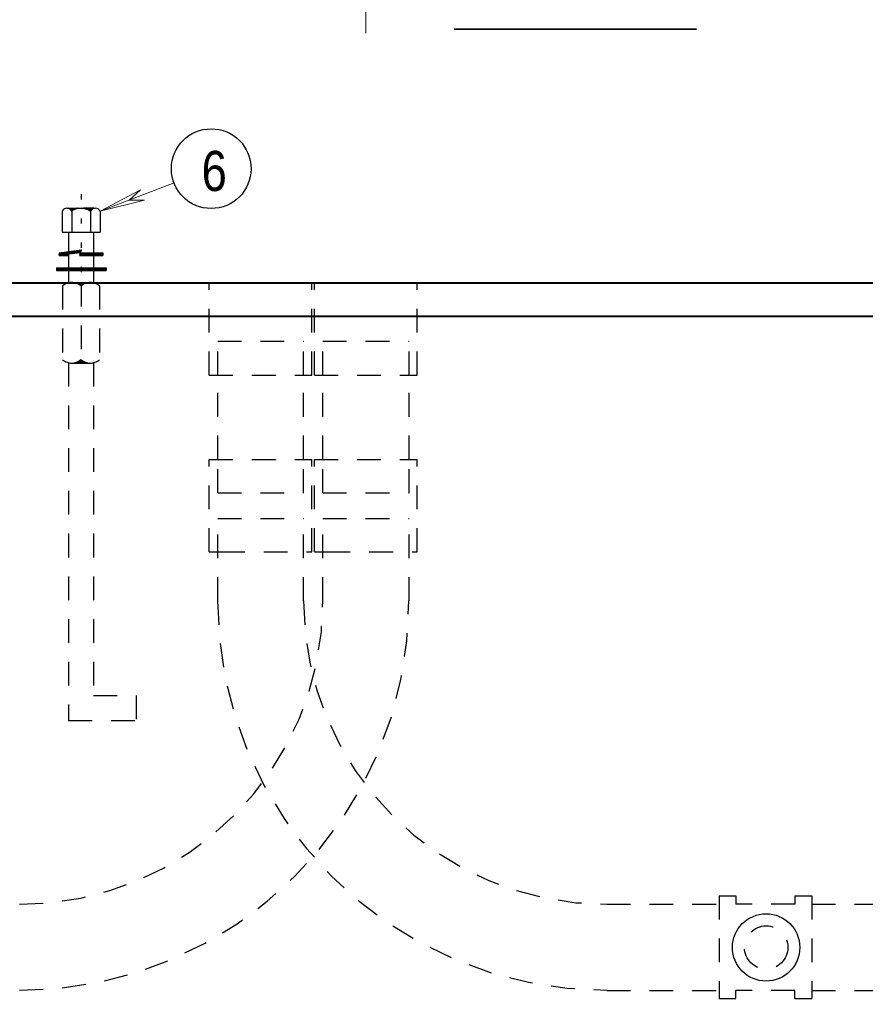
# Model space of a CAD drawing. Extents: x 312583 to 312854, y 144419 to 144597.
# Drawn here: x 312801.16 to 312817.2, y 144530.65 to 144549.21 of the extents above; entities that cross this region are included whole.
import ezdxf

# ---------------------------------------------------------------- set-up
doc = ezdxf.new("R2010")
doc.units = 0
doc.header["$LTSCALE"] = 0.3
doc.linetypes.add('DOTTED', pattern=[1.5, 0.3, -1.2])
doc.linetypes.add('SHORT_DASHED', pattern=[2.7, 1.5, -1.2])
doc.layers.add('1', color=7, linetype='Continuous', lineweight=25)
doc.layers.add('2', color=7, linetype='Continuous', lineweight=13)

msp = doc.modelspace()

# ---------------------------------------------------------------- linework, layer by layer
at = {"layer": '1', "linetype": 'DOTTED'}
msp.add_line((312802.3276, 144545.9033), (312802.3276, 144544.2243), dxfattribs=at)
at = {"layer": '1'}
for p, q in [((312801.9673, 144545.5813), (312801.9673, 144545.1826)), ((312802.0593, 144545.6349), (312802.596, 144545.6349)), ((312802.1513, 144545.5813), (312802.1513, 144545.1826)), ((312802.504, 144545.5813), (312802.504, 144545.1826)), ((312802.688, 144545.5813), (312802.688, 144545.1826)), ((312801.9673, 144545.1826), (312802.688, 144545.1826)), ((312802.09, 144545.1826), (312802.09, 144544.2243)), ((312802.5653, 144545.1826), (312802.5653, 144544.2243)), ((312801.9136, 144544.7916), (312801.9136, 144544.7379)), ((312802.3123, 144544.7916), (312802.7416, 144544.7916)), ((312802.7416, 144544.7916), (312802.7416, 144544.7379)), ((312802.297, 144544.7379), (312802.7416, 144544.7379)), ((312801.86, 144544.5079), (312802.803, 144544.5079)), ((312801.86, 144544.5079), (312801.86, 144544.4543)), ((312801.86, 144544.4926), (312802.803, 144544.4926)), ((312801.86, 144544.4773), (312802.803, 144544.4773)), ((312801.86, 144544.4619), (312802.803, 144544.4619)), ((312801.86, 144544.4543), (312802.803, 144544.4543)), ((312802.803, 144544.5079), (312802.803, 144544.4543)), ((312802.09, 144544.2243), (312802.5653, 144544.2243)), ((312802.1513, 144544.2243), (312802.504, 144544.2243))]:
    msp.add_line(p, q, dxfattribs=at)
at = {"layer": '1', "lineweight": 40}
for p, q in [((312778.6606, 144544.2243), (312839.994, 144544.2243)), ((312794.3773, 144543.5879), (312818.19, 144543.5879))]:
    msp.add_line(p, q, dxfattribs=at)
at = {"layer": '1', "linetype": 'SHORT_DASHED'}
for p, q in [((312801.975, 144544.1629), (312801.975, 144542.7676)), ((312802.3276, 144544.2243), (312802.3276, 144542.6986)), ((312802.6803, 144544.1629), (312802.6803, 144542.7676)), ((312804.758, 144542.4686), (312804.758, 144544.2243)), ((312806.7053, 144542.4686), (312806.7053, 144544.2243)), ((312806.7513, 144542.4686), (312806.7513, 144544.2243)), ((312808.6986, 144542.4686), (312808.6986, 144544.2243)), ((312804.919, 144543.1126), (312806.5443, 144543.1126)), ((312804.919, 144542.4686), (312804.919, 144543.1126)), ((312806.5443, 144542.4686), (312806.5443, 144543.1126)), ((312806.9123, 144543.1126), (312808.5453, 144543.1126)), ((312806.9123, 144542.4686), (312806.9123, 144543.1126)), ((312808.5453, 144542.4686), (312808.5453, 144543.1126)), ((312802.09, 144542.7063), (312802.09, 144535.9213)), ((312802.1513, 144542.6986), (312802.504, 144542.6986)), ((312802.5653, 144542.7063), (312802.5653, 144536.3966)), ((312804.758, 144542.4686), (312806.7053, 144542.4686)), ((312804.919, 144540.8739), (312804.919, 144542.4686)), ((312806.5443, 144540.8739), (312806.5443, 144542.4686)), ((312806.7513, 144542.4686), (312808.6986, 144542.4686)), ((312806.9123, 144540.8739), (312806.9123, 144542.4686)), ((312808.5453, 144540.8739), (312808.5453, 144542.4686)), ((312804.758, 144539.1183), (312804.758, 144540.8739)), ((312804.758, 144540.8739), (312806.7053, 144540.8739)), ((312804.919, 144540.2376), (312804.919, 144540.8739)), ((312806.5443, 144540.2376), (312806.5443, 144540.8739)), ((312806.7513, 144539.1183), (312806.7513, 144540.8739)), ((312806.7513, 144540.8739), (312808.6986, 144540.8739)), ((312806.9123, 144540.2376), (312806.9123, 144540.8739)), ((312808.5453, 144540.2376), (312808.5453, 144540.8739)), ((312804.919, 144540.2376), (312806.5443, 144540.2376)), ((312806.9123, 144540.2376), (312808.5453, 144540.2376)), ((312804.919, 144539.7546), (312806.5443, 144539.7546)), ((312804.919, 144538.1906), (312804.919, 144539.7546)), ((312806.5443, 144538.1906), (312806.5443, 144539.7546)), ((312806.9123, 144539.7546), (312808.5453, 144539.7546)), ((312806.9123, 144538.1906), (312806.9123, 144539.7546)), ((312808.5453, 144538.1906), (312808.5453, 144539.7546)), ((312802.09, 144535.9213), (312803.3703, 144535.9213)), ((312814.4256, 144532.6016), (312814.4256, 144530.6543)), ((312814.4256, 144532.6016), (312814.74, 144532.6016)), ((312814.74, 144532.6016), (312814.74, 144532.4406)), ((312815.8593, 144532.6016), (312815.8593, 144532.4406)), ((312815.8593, 144532.6016), (312816.1813, 144532.6016)), ((312816.1813, 144532.6016), (312816.1813, 144530.6543)), ((312812.2943, 144532.4406), (312814.4256, 144532.4406)), ((312815.8593, 144532.4406), (312814.74, 144532.4406)), ((312816.1813, 144532.4406), (312818.0136, 144532.4406)), ((312812.2943, 144530.8076), (312814.4256, 144530.8076)), ((312814.74, 144530.6543), (312814.74, 144530.8076)), ((312815.8593, 144530.8076), (312814.74, 144530.8076)), ((312815.8593, 144530.6543), (312815.8593, 144530.8076)), ((312816.1813, 144530.8076), (312818.0136, 144530.8076)), ((312814.4256, 144530.6543), (312814.74, 144530.6543)), ((312815.8593, 144530.6543), (312816.1813, 144530.6543))]:
    msp.add_line(p, q, dxfattribs=at)
at = {"layer": '1'}
for points in [[(312802.0823, 144545.6349), (312802.2816, 144545.6349), (312802.251, 144545.6273), (312802.228, 144545.6196), (312802.1896, 144545.6119), (312802.1513, 144545.5813), (312802.136, 144545.6043), (312802.1206, 144545.6196), (312802.09, 144545.6349), (312802.2663, 144545.6349), (312802.2203, 144545.6196), (312802.182, 144545.6043), (312802.1513, 144545.5889), (312802.1206, 144545.6196), (312802.1053, 144545.6273), (312802.2433, 144545.6349), (312802.1973, 144545.6196), (312802.1513, 144545.5966), (312802.113, 144545.6273), (312802.228, 144545.6273), (312802.1513, 144545.5966), (312802.1206, 144545.6273), (312802.2126, 144545.6273), (312802.1513, 144545.6043), (312802.1283, 144545.6273), (312802.205, 144545.6273), (312802.1513, 144545.6043), (312802.136, 144545.6196), (312802.182, 144545.6196), (312802.1513, 144545.6119), (312802.1436, 144545.6196), (312802.1666, 144545.6196), (312802.1513, 144545.6119)], [(312802.573, 144545.6349), (312802.3736, 144545.6349), (312802.412, 144545.6273), (312802.4273, 144545.6196), (312802.4656, 144545.6119), (312802.504, 144545.5813), (312802.5193, 144545.6043), (312802.5346, 144545.6196), (312802.5653, 144545.6349), (312802.389, 144545.6349), (312802.4426, 144545.6196), (312802.4733, 144545.6043), (312802.504, 144545.5889), (312802.5346, 144545.6196), (312802.55, 144545.6273), (312802.412, 144545.6349), (312802.458, 144545.6196), (312802.504, 144545.5966), (312802.5423, 144545.6273), (312802.4273, 144545.6273), (312802.504, 144545.5966), (312802.5346, 144545.6273), (312802.4426, 144545.6273), (312802.5116, 144545.6043), (312802.527, 144545.6273), (312802.458, 144545.6273), (312802.504, 144545.6043), (312802.5193, 144545.6196), (312802.4733, 144545.6196), (312802.504, 144545.6119), (312802.5116, 144545.6196), (312802.4886, 144545.6196), (312802.504, 144545.6119)], [(312801.9136, 144544.7916), (312802.3276, 144544.8453), (312802.297, 144544.7379)], [(312802.09, 144544.7379), (312801.9136, 144544.7456), (312801.9213, 144544.7839), (312802.32, 144544.8376), (312802.3046, 144544.7993), (312802.09, 144544.7686), (312802.0823, 144544.7456), (312801.9213, 144544.7456), (312801.929, 144544.7763), (312802.3046, 144544.8299), (312802.297, 144544.7993), (312802.0746, 144544.7686), (312802.0746, 144544.7456), (312801.929, 144544.7533), (312801.929, 144544.7686), (312802.2893, 144544.8223), (312802.2893, 144544.8146), (312802.0823, 144544.7686), (312802.067, 144544.7686), (312802.021, 144544.7533), (312801.9366, 144544.7609), (312802.2816, 144544.8146), (312801.9903, 144544.7609)], [(312802.3123, 144544.7916), (312801.9136, 144544.7379), (312802.09, 144544.7379)], [(312802.3046, 144544.7379), (312802.734, 144544.7379), (312802.734, 144544.7839), (312802.32, 144544.7839), (312802.3046, 144544.7456), (312802.7263, 144544.7456), (312802.7263, 144544.7763), (312802.32, 144544.7763), (312802.3123, 144544.7533), (312802.7186, 144544.7533), (312802.711, 144544.7686), (312802.711, 144544.7686), (312802.3276, 144544.7686), (312802.32, 144544.7609), (312802.711, 144544.7609)]]:
    msp.add_lwpolyline(points, dxfattribs=at)
at = {"layer": '1', "linetype": 'SHORT_DASHED'}
for points in [[(312802.1973, 144544.2243), (312802.458, 144544.2243), (312802.4273, 144544.2166), (312802.4043, 144544.2089), (312802.3736, 144544.2013), (312802.3583, 144544.1859), (312802.3276, 144544.1706), (312802.3276, 144544.1706), (312802.2816, 144544.2013), (312802.2356, 144544.2166), (312802.2126, 144544.2243), (312802.4426, 144544.2243), (312802.4196, 144544.2243), (312802.4043, 144544.2166), (312802.3736, 144544.2089), (312802.343, 144544.1936), (312802.3353, 144544.1859), (312802.3276, 144544.1706), (312802.2816, 144544.2013), (312802.2356, 144544.2166), (312802.4043, 144544.2243), (312802.366, 144544.2089), (312802.3276, 144544.1859), (312802.251, 144544.2166), (312802.389, 144544.2166), (312802.3276, 144544.1783), (312802.2663, 144544.2166), (312802.3813, 144544.2166), (312802.3353, 144544.1936), (312802.2893, 144544.2089), (312802.3583, 144544.2089), (312802.3276, 144544.2013), (312802.2893, 144544.2089), (312802.3123, 144544.1936), (312802.32, 144544.2089), (312802.3276, 144544.1859), (312802.343, 144544.2013), (312802.3506, 144544.2013), (312802.366, 144544.2089)], [(312802.1973, 144542.7063), (312802.458, 144542.6986), (312802.4273, 144542.7063), (312802.4043, 144542.7139), (312802.3736, 144542.7293), (312802.3583, 144542.7369), (312802.3276, 144542.7523), (312802.3276, 144542.7599), (312802.2816, 144542.7293), (312802.2356, 144542.7139), (312802.2126, 144542.7063), (312802.4426, 144542.7063), (312802.4196, 144542.7063), (312802.4043, 144542.7139), (312802.3736, 144542.7216), (312802.343, 144542.7369), (312802.3353, 144542.7446), (312802.3276, 144542.7523), (312802.2816, 144542.7216), (312802.2356, 144542.7063), (312802.4043, 144542.7063), (312802.366, 144542.7216), (312802.3276, 144542.7446), (312802.251, 144542.7139), (312802.389, 144542.7063), (312802.3276, 144542.7446), (312802.2663, 144542.7139), (312802.3813, 144542.7139), (312802.3353, 144542.7369), (312802.2893, 144542.7139), (312802.3583, 144542.7139), (312802.3276, 144542.7293), (312802.2893, 144542.7216), (312802.3123, 144542.7369), (312802.32, 144542.7216), (312802.3276, 144542.7446), (312802.343, 144542.7216), (312802.3506, 144542.7216), (312802.366, 144542.7216)], [(312804.758, 144539.1183), (312804.9803, 144539.1183), (312806.7053, 144539.1183), (312806.7053, 144540.8739)], [(312806.7513, 144539.1183), (312806.9813, 144539.1183), (312808.6986, 144539.1183), (312808.6986, 144540.8739)], [(312802.5653, 144536.3966), (312803.3703, 144536.3966), (312803.3703, 144535.9213)]]:
    msp.add_lwpolyline(points, dxfattribs=at)
at = {"layer": '1'}
msp.add_circle((312815.3137, 144531.6209), 0.6389, dxfattribs=at)
at = {"layer": '1', "linetype": 'SHORT_DASHED'}
msp.add_circle((312815.3137, 144531.6209), 0.4108, dxfattribs=at)
at = {"layer": '1'}
for centre, radius, start, end in [((312802.0596, 144545.5372), 0.0993, 25.60064, 154.39936), ((312802.3283, 144545.3239), 0.3126, 55.04559, 124.95441), ((312802.5969, 144545.5372), 0.0993, 25.60064, 154.39936)]:
    msp.add_arc(centre, radius, start, end, dxfattribs=at)
at = {"layer": '1', "linetype": 'SHORT_DASHED'}
for centre, radius, start, end in [((312802.1535, 144543.9547), 0.272, 50.00693, 129.99306), ((312802.503, 144543.9547), 0.272, 50.00694, 129.99307), ((312802.1535, 144542.9721), 0.272, 230.00694, 309.99307), ((312802.503, 144542.9721), 0.272, 230.00693, 309.99306), ((312801.1629, 144538.1893), 5.75, 270, 0), ((312801.1629, 144538.1893), 7.3792, 270, 0), ((312812.2949, 144538.1893), 7.3792, 180, 270), ((312812.2949, 144538.1893), 5.75, 180, 270)]:
    msp.add_arc(centre, radius, start, end, dxfattribs=at)
at = {"layer": '2'}
for p, q in [((312807.725, 144561.5586), (312807.725, 144548.9546)), ((312804.091, 144546.1179), (312802.688, 144545.5813)), ((312802.688, 144545.5813), (312803.4546, 144545.9876)), ((312803.4546, 144545.9876), (312803.24, 144545.7883)), ((312802.688, 144545.5813), (312803.5313, 144545.7883)), ((312803.5313, 144545.7883), (312803.24, 144545.7883))]:
    msp.add_line(p, q, dxfattribs=at)
at = {"layer": '2', "lineweight": 35}
msp.add_line((312809.4015, 144549.0333), (312813.9967, 144549.0333), dxfattribs=at)
at = {"layer": '2', "lineweight": 25}
msp.add_circle((312804.7957, 144546.3856), 0.7557, dxfattribs=at)

# ---------------------------------------------------------------- texts
at = {"layer": '2', "width": 0.85}
msp.add_text('6', height=0.76, dxfattribs=at).set_placement((312804.6119, 144545.9628))

doc.saveas('drawing.dxf')
